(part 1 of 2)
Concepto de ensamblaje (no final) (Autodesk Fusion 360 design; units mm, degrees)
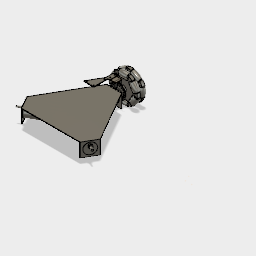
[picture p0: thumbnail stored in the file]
sketch "Sketch1" plane through (0, 0, 0) normal (0, 1, 0) x axis (1, 0, 0)
  line L1 (25, 130) -> (-25, 130)
  line L2 (-125.0833, -43.3494) -> (-25, 130)
  line L3 (100.0833, -86.6506) -> (-100.0833, -86.6506)
  line L4 (25, 130) -> (125.0833, -43.3494)
  line L5 (100.0833, -86.6506) -> (125.0833, -43.3494)
  line L6 (-125.0833, -43.3494) -> (-100.0833, -86.6506)
  line L7 (-50.0833, -86.6506) -> (-100.0833, -86.6506)
  point P3 (-25, 130)
  point P4 (25, 130)
  point P6 (125.0833, -43.3494)
  point P7 (100.0833, -86.6506)
  point P8 (-100.0833, -86.6506)
  point P9 (-125.0833, -43.3494)
  dimension "d2" distance P3 P4 = 50
  dimension "d8" distance P6 P7 = 50
  dimension "d11" distance P8 P9 = 50
  dimension "d12" distance P3 P9 = 200.1666
  dimension "d13" distance P7 P8 = 200.1666
  dimension "d14" distance P4 P6 = 200.1666
extrude "Extrude1" new body sketch "Sketch1" profile of L1 L2 L3 L4 L5 L6 along normal blind 2
sketch "Sketch2" plane through (0, 0, 0) normal (0, -1, 0) x axis (1, 0, 0)
  line L1 (125.0833, 43.3494) -> (25, -130)
  line L2 (100.0833, 86.6506) -> (125.0833, 43.3494)
  line L3 (-100.0833, 86.6506) -> (100.0833, 86.6506)
  line L4 (-125.0833, 43.3494) -> (-100.0833, 86.6506)
  line L5 (-25, -130) -> (-125.0833, 43.3494)
  line L6 (25, -130) -> (-25, -130)
  line L7 (-25, -130) -> (-26.165, -127.9822)
  line L8 (26.1498, -128.0085) -> (25, -130)
  line L9 (-26.165, -127.9822) -> (26.1498, -128.0085)
extrude "Extrude2" add sketch "Sketch2" profile of L1 L5 L6 L7 L8 L9 along normal blind 50
sketch "Sketch3" plane through (0, 0, 0) normal (0, -1, 0) x axis (1, 0, 0)
  line L1 (26.1498, -128.0085) -> (-26.165, -127.9822)
  line L2 (125.0833, 43.3494) -> (26.1498, -128.0085)
  line L3 (100.0833, 86.6506) -> (125.0833, 43.3494)
  line L4 (-100.0833, 86.6506) -> (100.0833, 86.6506)
  line L5 (-125.0833, 43.3494) -> (-100.0833, 86.6506)
  line L6 (-26.165, -127.9822) -> (-125.0833, 43.3494)
  line L7 (125.0833, 43.3494) -> (123.9286, 41.3494)
  line L8 (100.0833, 86.6506) -> (97.7739, 86.6506)
  line L9 (123.9286, 41.3494) -> (97.7739, 86.6506)
  line L10 (-100.0833, 86.6506) -> (-97.7739, 86.6506)
  line L11 (-125.0833, 43.3494) -> (-123.9328, 41.3566)
  line L12 (-97.7739, 86.6506) -> (-123.9328, 41.3566)
extrude "Extrude3" cut of existing geometry blind -5
extrude "Extrude4" add sketch "Sketch3" profile of L2 L3 L4 L5 L6 L7 L8 L9 L10 L11 L12 along normal blind 45
move "Move1"
sketch "Sketch4" plane through (112.5833, 0, 65) normal (0.866, 0, 0.5) x axis (0.5, 0, -0.866)
  line L1 (25, 47) -> (25, 0)
  line L2 (-25, 47) -> (25, 47)
  line L3 (-25, 0) -> (-25, 47)
  line L4 (25, 0) -> (-25, 0)
  line L5 (0, 37.9) -> (0, 42.5)
  circle C1 centre (0, 24) radius 18.5
  circle C2 centre (0, 31.9) radius 6
  point P6 (0, 24)
  point P7 (0, 42.5)
  point P8 (0, 37.9)
  dimension "d31" diameter C1 = 37
  dimension "d32" distance L2 P6 = 23
  dimension "d33" distance L3 P6 = 25
  dimension "d35" distance P7 P8 = 4.6
  dimension "d36" diameter C2 = 12
extrude "Extrude5" cut sketch "Sketch4" profile of C1 C2 against normal blind 0.1
extrude "Extrude6" cut of existing geometry blind -2
sketch "Sketch5" plane through (-112.5833, 0, 65) normal (-0.866, 0, 0.5) x axis (0.5, 0, 0.866)
  line L1 (25, 47) -> (25, 0)
  line L2 (-25, 47) -> (25, 47)
  line L3 (-25, 0) -> (-25, 47)
  line L4 (25, 0) -> (-25, 0)
  line L5 (0, 37.9) -> (0, 42.5)
  circle C1 centre (0, 24) radius 18.5
  circle C2 centre (0, 31.9) radius 6
  point P6 (0, 24)
  point P7 (0, 42.5)
  point P8 (0, 37.9)
  dimension "d41" diameter C1 = 37
  dimension "d42" distance L2 P6 = 23
  dimension "d43" distance L3 P6 = 25
  dimension "d44" distance L4 P6 = 24
  dimension "d45" distance P7 P8 = 4.6
  dimension "d46" diameter C2 = 12
extrude "Extrude7" cut sketch "Sketch5" profile of C1 C2 against normal blind 0.1
extrude "Extrude8" cut of existing geometry blind -2
sketch "Sketch6" plane through (0, 0, -130) normal (0, 0, -1) x axis (-1, 0, 0)
  line L1 (25, 0) -> (-25, 0)
  line L2 (25, 47) -> (25, 0)
  line L3 (-25, 47) -> (25, 47)
  line L4 (-25, 0) -> (-25, 47)
  circle C1 centre (0, 24) radius 18.5
  circle C2 centre (0, 31.9) radius 6
  point P6 (0, 24)
  dimension "d51" diameter C1 = 37
  dimension "d52" distance L3 P6 = 23
  dimension "d53" distance L4 P6 = 25
  dimension "d55" diameter C2 = 12
extrude "Extrude9" cut sketch "Sketch6" profile of C1 C2 against normal blind 0.1
hole "Hole1" HoleDepth 6 HoleDiameter 12 TipAngle 118
sketch "Sketch7" plane through (0, 0, -130) normal (0, 0, -1) x axis (-1, 0, 0)
  line L1 (25, 0) -> (-25, 0)
  line L2 (25, 47) -> (25, 0)
  line L3 (-25, 47) -> (25, 47)
  line L4 (-25, 0) -> (-25, 47)
  circle C1 centre (0, 24) radius 18.5
sketch "Sketch8" plane through (0, 0, 0) normal (1, 0, 0) x axis (0, 0, -1)
sketch "Sketch1"
  circle C1 centre (170, 18.5) radius 18.5
  dimension "d61" diameter C1 = 37
extrude "Extrude1" new body sketch "Sketch1" blind 54.5
sketch "Sketch2" plane through (0, 0, 0) normal (0, 0, -1) x axis (-1, 0, 0)
  circle C1 centre (-170, 18.5) radius 18.5
  circle C2 centre (-170, 26.4) radius 6
  dimension "d66" diameter C2 = 12
extrude "Extrude2" add sketch "Sketch2" profile of C2 along normal blind 6.5
sketch "Sketch3" plane through (0, 0, -6.5) normal (0, 0, -1) x axis (-1, 0, 0)
  circle C1 centre (-170, 26.4) radius 6
  circle C2 centre (-170, 26.4) radius 3
  dimension "d69" diameter C2 = 6
extrude "Extrude3" add sketch "Sketch3" profile of C2 along normal blind 14.5
sketch "Sketch1" plane through (0, 0, 0) normal (0, 1, 0) x axis (1, 0, 0)
sketch "Sketch2" plane through (0, 0, 0) normal (1, 0, 0) x axis (0, 0, -1)
copy_paste_bodies "CopyPasteBodies1"
move "Move1"
copy_paste_bodies "CopyPasteBodies1"
move "Move1"
move "Move1"
position "Position1"
joint "Assemble1" alignAngle 0 alignOffsetX 0 alignOffsetY 0 alignOffsetZ 0
joint "Assemble2" alignAngle 0 alignOffsetX 0 alignOffsetY 0 alignOffsetZ 0
joint "Assemble3" alignAngle 180 alignOffsetX 0 alignOffsetY 0 alignOffsetZ 0
sketch "Sketch1"
  line L1 (233, 59.45) -> (233, 66.5)
  line L2 (235.9, 54.4271) -> (233, 59.45)
  line L3 (233, 70) -> (233, 66.5)
  line L4 (235, 66.5) -> (233, 66.5)
  line L5 (235, 72.697) -> (235, 66.5)
  line L6 (233, 65.5) -> (250, 65.5)
  line L7 (265, 66.5) -> (267, 66.5)
  line L8 (267, 59.45) -> (267, 66.5)
  line L9 (265, 72.697) -> (265, 66.5)
  line L10 (264.1, 54.4271) -> (267, 59.45)
  line L11 (267, 65.5) -> (250, 65.5)
  line L12 (267, 70) -> (267, 66.5)
  line L13 (264.1, 54.4271) -> (235.9, 54.4271)
  line L14 (202.5289, 32.7776) -> (205.5599, 31.0276)
  line L15 (211.6654, 27.5026) -> (205.5599, 31.0276)
  line L16 (231.5654, 51.9245) -> (228.6654, 56.9474)
  line L17 (206.426, 30.5276) -> (214.926, 45.25)
  line L18 (231.5654, 51.9245) -> (217.4654, 27.5026)
  line L19 (217.4654, 27.5026) -> (211.6654, 27.5026)
  line L20 (228.6654, 56.9474) -> (222.5599, 60.4724)
  line L21 (201.1932, 35.8581) -> (206.5599, 32.7596)
  line L22 (223.426, 59.9724) -> (214.926, 45.25)
  line L23 (216.1932, 61.8389) -> (221.5599, 58.7404)
  line L24 (221.5599, 58.7404) -> (222.5599, 60.4724)
  line L25 (206.5599, 32.7596) -> (205.5599, 31.0276)
  line L26 (219.5289, 62.2224) -> (222.5599, 60.4724)
  line L27 (219.5289, -12.2224) -> (222.5599, -10.4724)
  line L28 (228.6654, -6.9474) -> (222.5599, -10.4724)
  line L29 (217.4654, 22.4974) -> (211.6654, 22.4974)
  line L30 (223.426, -9.9724) -> (214.926, 4.75)
  line L31 (217.4654, 22.4974) -> (231.5654, -1.9245)
  line L32 (231.5654, -1.9245) -> (228.6654, -6.9474)
  line L33 (211.6654, 22.4974) -> (205.5599, 18.9724)
  line L34 (216.1932, -11.8389) -> (221.5599, -8.7404)
  line L35 (206.426, 19.4724) -> (214.926, 4.75)
  line L36 (201.1932, 14.1419) -> (206.5599, 17.2404)
  line L37 (206.5599, 17.2404) -> (205.5599, 18.9724)
  line L38 (221.5599, -8.7404) -> (222.5599, -10.4724)
  line L39 (202.5289, 17.2224) -> (205.5599, 18.9724)
  line L40 (267, -20) -> (267, -16.5)
  line L41 (267, -9.45) -> (267, -16.5)
  line L42 (235.9, -4.4271) -> (233, -9.45)
  line L43 (267, -15.5) -> (250, -15.5)
  line L44 (235.9, -4.4271) -> (264.1, -4.4271)
  line L45 (264.1, -4.4271) -> (267, -9.45)
  line L46 (233, -9.45) -> (233, -16.5)
  line L47 (265, -22.697) -> (265, -16.5)
  line L48 (233, -15.5) -> (250, -15.5)
  line L49 (235, -22.697) -> (235, -16.5)
  line L50 (235, -16.5) -> (233, -16.5)
  line L51 (265, -16.5) -> (267, -16.5)
  line L52 (233, -20) -> (233, -16.5)
  line L53 (297.4711, 17.2224) -> (294.4401, 18.9724)
  line L54 (288.3346, 22.4974) -> (294.4401, 18.9724)
  line L55 (268.4346, -1.9245) -> (271.3346, -6.9474)
  line L56 (293.574, 19.4724) -> (285.074, 4.75)
  line L57 (268.4346, -1.9245) -> (282.5346, 22.4974)
  line L58 (282.5346, 22.4974) -> (288.3346, 22.4974)
  line L59 (271.3346, -6.9474) -> (277.4401, -10.4724)
  line L60 (298.8068, 14.1419) -> (293.4401, 17.2404)
  line L61 (276.574, -9.9724) -> (285.074, 4.75)
  line L62 (283.8068, -11.8389) -> (278.4401, -8.7404)
  line L63 (278.4401, -8.7404) -> (277.4401, -10.4724)
  line L64 (293.4401, 17.2404) -> (294.4401, 18.9724)
  line L65 (280.4711, -12.2224) -> (277.4401, -10.4724)
  line L66 (280.4711, 62.2224) -> (277.4401, 60.4724)
  line L67 (271.3346, 56.9474) -> (277.4401, 60.4724)
  line L68 (282.5346, 27.5026) -> (288.3346, 27.5026)
  line L69 (276.574, 59.9724) -> (285.074, 45.25)
  line L70 (282.5346, 27.5026) -> (268.4346, 51.9245)
  line L71 (268.4346, 51.9245) -> (271.3346, 56.9474)
  line L72 (288.3346, 27.5026) -> (294.4401, 31.0276)
  line L73 (283.8068, 61.8389) -> (278.4401, 58.7404)
  line L74 (293.574, 30.5276) -> (285.074, 45.25)
  line L75 (298.8068, 35.8581) -> (293.4401, 32.7596)
  line L76 (293.4401, 32.7596) -> (294.4401, 31.0276)
  line L77 (278.4401, 58.7404) -> (277.4401, 60.4724)
  line L78 (297.4711, 32.7776) -> (294.4401, 31.0276)
  arc A1 centre (250, 25) radius 50 clockwise from (235, 72.697) to (265, 72.697)
  arc A2 centre (250, 25) radius 50 clockwise from (201.1932, 35.8581) to (216.1932, 61.8389)
  arc A3 centre (250, 25) radius 50 clockwise from (216.1932, -11.8389) to (201.1932, 14.1419)
  arc A4 centre (250, 25) radius 50 clockwise from (265, -22.697) to (235, -22.697)
  arc A5 centre (250, 25) radius 50 clockwise from (298.8068, 14.1419) to (283.8068, -11.8389)
  arc A6 centre (250, 25) radius 50 clockwise from (283.8068, 61.8389) to (298.8068, 35.8581)
  arc A7 centre (250, 25) radius 48.1041 clockwise from (202.5289, 17.2224) to (202.5289, 32.7776)
  arc A8 centre (250, 25) radius 48.1041 clockwise from (233, -20) to (219.5289, -12.2224)
  arc A9 centre (250, 25) radius 48.1041 clockwise from (280.4711, -12.2224) to (267, -20)
  arc A10 centre (250, 25) radius 48.1041 clockwise from (297.4711, 32.7776) to (297.4711, 17.2224)
  arc A11 centre (250, 25) radius 48.1041 clockwise from (267, 70) to (280.4711, 62.2224)
  arc A12 centre (250, 25) radius 48.1041 clockwise from (219.5289, 62.2224) to (233, 70)
  point P3 (233, 66.5)
  point P4 (233, 59.45)
  point P5 (235.9, 54.4271)
  point P6 (233, 70)
  point P2 (250, 65.5)
  point P15 (250, 75)
  point P8 (235, 72.697)
  dimension "d112" distance P3 P4 = 7.05
  dimension "d114" distance P4 P5 = 5.8
  dimension "d115" distance P3 P6 = 3.5
  dimension "d116" distance L4 L6 = 1
  dimension "d117" distance P2 P15 = 9.5
  dimension "d118" distance P8 L6 = 7.197
extrude "Extrude1" new body sketch "Sketch1" profile of L1 L2 L3 L8 L10 L12 L13 L14 L15 L16 L18 L19 L20 L26 L27 L28 L29 L31 L32 L33 L39 L40 L41 L42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 blind 5
sketch "Sketch3" plane through (0, 0, 119.3234) normal (0, 0, -1) x axis (-1, 0, 0)
  circle C1 centre (-17.736, 26.4) radius 3
revolve "Revolve1" sketch "Sketch1" AlongAngle 360
revolve "Revolve3" sketch "Sketch1" AlongAngle 360
revolve "Revolve4" sketch "Sketch1" AlongAngle 360
revolve "Revolve2" sketch "Sketch1" AlongAngle 360
revolve "Revolve5" sketch "Sketch1" AlongAngle 360
revolve "Revolve6" sketch "Sketch1" AlongAngle 360
extrude "Extrude2" cut of existing geometry blind -5
extrude "Extrude3" add sketch "Sketch1" profile of L1 L2 L3 L8 L10 L12 L13 L14 L15 L16 L18 L19 L20 L26 L27 L28 L29 L31 L32 L33 L39 L40 L41 L42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 distance 5
sketch "Sketch2" plane through (0, 0, 5) normal (0, 0, 1) x axis (1, 0, 0)
  line L1 (233, 70) -> (233, 59.45)
  line L2 (228.6654, 56.9474) -> (219.5289, 62.2224)
  line L3 (231.5654, 51.9245) -> (228.6654, 56.9474)
  line L4 (217.4654, 27.5026) -> (231.5654, 51.9245)
  line L5 (211.6654, 27.5026) -> (217.4654, 27.5026)
  line L6 (202.5289, 32.7776) -> (211.6654, 27.5026)
  line L7 (211.6654, 22.4974) -> (202.5289, 17.2224)
  line L8 (217.4654, 22.4974) -> (211.6654, 22.4974)
  line L9 (231.5654, -1.9245) -> (217.4654, 22.4974)
  line L10 (228.6654, -6.9474) -> (231.5654, -1.9245)
  line L11 (219.5289, -12.2224) -> (228.6654, -6.9474)
  line L12 (233, -9.45) -> (233, -20)
  line L13 (235.9, -4.4271) -> (233, -9.45)
  line L14 (264.1, -4.4271) -> (235.9, -4.4271)
  line L15 (267, -9.45) -> (264.1, -4.4271)
  line L16 (267, -20) -> (267, -9.45)
  line L17 (271.3346, -6.9474) -> (280.4711, -12.2224)
  line L18 (268.4346, -1.9245) -> (271.3346, -6.9474)
  line L19 (282.5346, 22.4974) -> (268.4346, -1.9245)
  line L20 (288.3346, 22.4974) -> (282.5346, 22.4974)
  line L21 (297.4711, 17.2224) -> (288.3346, 22.4974)
  line L22 (288.3346, 27.5026) -> (297.4711, 32.7776)
  line L23 (282.5346, 27.5026) -> (288.3346, 27.5026)
  line L24 (268.4346, 51.9245) -> (282.5346, 27.5026)
  line L25 (271.3346, 56.9474) -> (268.4346, 51.9245)
  line L26 (280.4711, 62.2224) -> (271.3346, 56.9474)
  line L27 (267, 59.45) -> (267, 70)
  line L28 (264.1, 54.4271) -> (267, 59.45)
  line L29 (235.9, 54.4271) -> (264.1, 54.4271)
  line L30 (233, 59.45) -> (235.9, 54.4271)
  arc A1 centre (250, 25) radius 48.1041 clockwise from (219.5289, 62.2224) to (233, 70)
  arc A2 centre (250, 25) radius 48.1041 clockwise from (202.5289, 17.2224) to (202.5289, 32.7776)
  arc A3 centre (250, 25) radius 48.1041 clockwise from (233, -20) to (219.5289, -12.2224)
  arc A4 centre (250, 25) radius 48.1041 clockwise from (280.4711, -12.2224) to (267, -20)
  arc A5 centre (250, 25) radius 48.1041 clockwise from (297.4711, 32.7776) to (297.4711, 17.2224)
  arc A6 centre (250, 25) radius 48.1041 clockwise from (267, 70) to (280.4711, 62.2224)
copy_paste_bodies "CopyPasteBodies1"
move "Move1"
move "Move2" RotateAngle -30
sketch "Sketch3" plane through (0, 0, -5) normal (0, 0, -1) x axis (-1, 0, 0)
  line L1 (-233, 59.45) -> (-233, 70)
  line L2 (-235.9, 54.4271) -> (-233, 59.45)
  line L3 (-264.1, 54.4271) -> (-235.9, 54.4271)
  line L4 (-267, 59.45) -> (-264.1, 54.4271)
  line L5 (-267, 70) -> (-267, 59.45)
  line L6 (-271.3346, 56.9474) -> (-280.4711, 62.2224)
  line L7 (-268.4346, 51.9245) -> (-271.3346, 56.9474)
  line L8 (-282.5346, 27.5026) -> (-268.4346, 51.9245)
  line L9 (-288.3346, 27.5026) -> (-282.5346, 27.5026)
  line L10 (-297.4711, 32.7776) -> (-288.3346, 27.5026)
  line L11 (-288.3346, 22.4974) -> (-297.4711, 17.2224)
  line L12 (-282.5346, 22.4974) -> (-288.3346, 22.4974)
  line L13 (-268.4346, -1.9245) -> (-282.5346, 22.4974)
  line L14 (-271.3346, -6.9474) -> (-268.4346, -1.9245)
  line L15 (-280.4711, -12.2224) -> (-271.3346, -6.9474)
  line L16 (-267, -9.45) -> (-267, -20)
  line L17 (-264.1, -4.4271) -> (-267, -9.45)
  line L18 (-235.9, -4.4271) -> (-264.1, -4.4271)
  line L19 (-233, -9.45) -> (-235.9, -4.4271)
  line L20 (-233, -20) -> (-233, -9.45)
  line L21 (-228.6654, -6.9474) -> (-219.5289, -12.2224)
  line L22 (-231.5654, -1.9245) -> (-228.6654, -6.9474)
  line L23 (-217.4654, 22.4974) -> (-231.5654, -1.9245)
  line L24 (-211.6654, 22.4974) -> (-217.4654, 22.4974)
  line L25 (-202.5289, 17.2224) -> (-211.6654, 22.4974)
  line L26 (-211.6654, 27.5026) -> (-202.5289, 32.7776)
  line L27 (-217.4654, 27.5026) -> (-211.6654, 27.5026)
  line L28 (-231.5654, 51.9245) -> (-217.4654, 27.5026)
  line L29 (-228.6654, 56.9474) -> (-231.5654, 51.9245)
  line L30 (-219.5289, 62.2224) -> (-228.6654, 56.9474)
  line L31 (-232.6795, 15) -> (-250, 5)
  line L32 (-232.6795, 35) -> (-232.6795, 15)
  line L33 (-250, 45) -> (-232.6795, 35)
  line L34 (-267.3205, 35) -> (-250, 45)
  line L35 (-267.3205, 15) -> (-267.3205, 35)
  line L36 (-250, 5) -> (-267.3205, 15)
  arc A1 centre (-250, 25) radius 48.1041 clockwise from (-280.4711, 62.2224) to (-267, 70)
  arc A2 centre (-250, 25) radius 48.1041 clockwise from (-297.4711, 17.2224) to (-297.4711, 32.7776)
  arc A3 centre (-250, 25) radius 48.1041 clockwise from (-267, -20) to (-280.4711, -12.2224)
  arc A4 centre (-250, 25) radius 48.1041 clockwise from (-219.5289, -12.2224) to (-233, -20)
  arc A5 centre (-250, 25) radius 48.1041 clockwise from (-202.5289, 32.7776) to (-202.5289, 17.2224)
  arc A6 centre (-250, 25) radius 48.1041 clockwise from (-233, 70) to (-219.5289, 62.2224)
  point P39 (-250, 5)
  point P45 (-250, 25)
  dimension "d135" distance P39 P45 = 20
extrude "Extrude4" add sketch "Sketch3" profile of L31 L32 L33 L34 L35 L36 along normal blind 12
sketch "Sketch1" plane through (0, 0, -3.4476) normal (0, 0, 1) x axis (1, 0, 0)
  line L1 (383.04, 72.4711) -> (377.765, 63.3346)
  line L2 (372.7599, 63.3346) -> (367.4849, 72.4711)
  line L3 (372.7599, 57.5346) -> (372.7599, 63.3346)
  line L4 (348.338, 43.4346) -> (372.7599, 57.5346)
  line L5 (343.315, 46.3346) -> (348.338, 43.4346)
  line L6 (338.04, 55.4711) -> (343.315, 46.3346)
  line L7 (340.8125, 42) -> (330.2625, 42)
  line L8 (345.8354, 39.1) -> (340.8125, 42)
  line L9 (345.8354, 10.9) -> (345.8354, 39.1)
  line L10 (340.8125, 8) -> (345.8354, 10.9)
  line L11 (330.2625, 8) -> (340.8125, 8)
  line L12 (343.315, 3.6654) -> (338.04, -5.4711)
  line L13 (348.338, 6.5654) -> (343.315, 3.6654)
  line L14 (372.7599, -7.5346) -> (348.338, 6.5654)
  line L15 (372.7599, -13.3346) -> (372.7599, -7.5346)
  line L16 (367.4849, -22.4711) -> (372.7599, -13.3346)
  line L17 (377.765, -13.3346) -> (383.04, -22.4711)
  line L18 (377.765, -7.5346) -> (377.765, -13.3346)
  line L19 (402.1869, 6.5654) -> (377.765, -7.5346)
  line L20 (407.2099, 3.6654) -> (402.1869, 6.5654)
  line L21 (412.4849, -5.4711) -> (407.2099, 3.6654)
  line L22 (409.7125, 8) -> (420.2625, 8)
  line L23 (404.6895, 10.9) -> (409.7125, 8)
  line L24 (404.6895, 39.1) -> (404.6895, 10.9)
  line L25 (409.7125, 42) -> (404.6895, 39.1)
  line L26 (420.2625, 42) -> (409.7125, 42)
  line L27 (407.2099, 46.3346) -> (412.4849, 55.4711)
  line L28 (402.1869, 43.4346) -> (407.2099, 46.3346)
  line L29 (377.765, 57.5346) -> (402.1869, 43.4346)
  line L30 (377.765, 63.3346) -> (377.765, 57.5346)
  line L31 (392.583, 15) -> (375.2625, 5)
  line L32 (392.583, 35) -> (392.583, 15)
  line L33 (375.2625, 45) -> (392.583, 35)
  line L34 (357.942, 35) -> (375.2625, 45)
  line L35 (357.942, 15) -> (357.942, 35)
  line L36 (375.2625, 5) -> (357.942, 15)
  arc A1 centre (375.2625, 25) radius 48.1041 clockwise from (367.4849, 72.4711) to (383.04, 72.4711)
  arc A2 centre (375.2625, 25) radius 48.1041 clockwise from (330.2625, 42) to (338.04, 55.4711)
  arc A3 centre (375.2625, 25) radius 48.1041 clockwise from (338.04, -5.4711) to (330.2625, 8)
  arc A4 centre (375.2625, 25) radius 48.1041 clockwise from (383.04, -22.4711) to (367.4849, -22.4711)
  arc A5 centre (375.2625, 25) radius 48.1041 clockwise from (420.2625, 8) to (412.4849, -5.4711)
  arc A6 centre (375.2625, 25) radius 48.1041 clockwise from (412.4849, 55.4711) to (420.2625, 42)
  point P39 (375.2625, 5)
  point P45 (375.2625, 25)
  dimension "d139" distance P39 P45 = 20
extrude "Extrude1" cut sketch "Sketch1" profile of L31 L32 L33 L34 L35 L36 against normal blind 3
sketch "Sketch4" plane through (0, 0, -17) normal (0, 0, -1) x axis (-1, 0, 0)
  line L1 (-250, 5) -> (-267.3205, 15)
  line L2 (-232.6795, 15) -> (-250, 5)
  line L3 (-232.6795, 35) -> (-232.6795, 15)
  line L4 (-250, 45) -> (-232.6795, 35)
  line L5 (-267.3205, 35) -> (-250, 45)
  line L6 (-267.3205, 15) -> (-267.3205, 35)
  circle C1 centre (-250, 37.5) radius 1.5
  circle C2 centre (-260.8253, 18.75) radius 1.5
  circle C3 centre (-239.1747, 18.75) radius 1.5
  dimension "d143" diameter C1 = 3
  dimension "d144" diameter C2 = 3
  dimension "d145" diameter C3 = 3
sketch "Sketch5" plane through (267.3205, 0, 0) normal (1, 0, 0) x axis (0, 0, -1)
  line L1 (5, 15) -> (5, 35)
  line L2 (17, 15) -> (5, 15)
  line L3 (17, 35) -> (17, 15)
  line L4 (5, 35) -> (17, 35)
  dimension "d148" distance L1 L3 = 12
extrude "Extrude5" cut sketch "Sketch4" profile of C1 C2 C3 against normal blind 10
sketch "Sketch2" plane through (0, 0, -6.4476) normal (0, 0, 1) x axis (1, 0, 0)
  line L1 (375.2625, 5) -> (357.942, 15)
  line L2 (392.583, 15) -> (375.2625, 5)
  line L3 (392.583, 35) -> (392.583, 15)
  line L4 (375.2625, 45) -> (392.583, 35)
  line L5 (357.942, 35) -> (375.2625, 45)
  line L6 (357.942, 15) -> (357.942, 35)
  circle C1 centre (375.2625, 37.5) radius 1.5
  circle C2 centre (386.0878, 18.75) radius 1.5
  circle C3 centre (364.4371, 18.75) radius 1.5
  dimension "d152" diameter C1 = 3
  dimension "d153" diameter C2 = 3
  dimension "d154" diameter C3 = 3
extrude "Extrude2" cut sketch "Sketch2" profile of C1 C2 C3 against normal blind 7
sketch "Sketch6" plane through (0, 0, -17) normal (0, 0, -1) x axis (-1, 0, 0)
  circle C1 centre (-260.8253, 18.75) radius 1.5
  circle C2 centre (-239.1747, 18.75) radius 1.5
  circle C3 centre (-250, 37.5) radius 1.5
cylinder_primitive "CylinderPrimitive2" Height 17 Diameter 3
sketch "Sketch3" plane through (0, 47, 0) normal (0, 1, 0) x axis (-1, 0, 0)
sketch "Sketch4" plane through (0, 0, 0) normal (0, 0, -1) x axis (-1, 0, 0)
  line L1 (-506, 4.9822) -> (-508.0154, 1.527)
  line L2 (-507.9846, 8.4552) -> (-506, 4.9822)
  line L3 (-511.9846, 8.473) -> (-507.9846, 8.4552)
  line L4 (-514, 5.0178) -> (-511.9846, 8.473)
  line L5 (-512.0154, 1.5448) -> (-514, 5.0178)
  line L6 (-508.0154, 1.527) -> (-512.0154, 1.5448)
  circle C1 centre (-510, 5) radius 1.5
  point P3 (-508.0154, 1.527)
  point P9 (-510, 5)
  dimension "d159" distance P3 P9 = 4
extrude "Extrude1" add sketch "Sketch4" along normal blind 2
thread "Thread2"
thread "Thread1"
thread "Thread2"
thread "Thread3"
copy_paste_bodies "CopyPasteBodies1"
move "Move1"
sketch "Sketch3" plane through (0, 0, -5) normal (0, 0, -1) x axis (-1, 0, 0)
  line L1 (-267.3205, 35) -> (-267.3205, 15)
  line L2 (-250, 45) -> (-267.3205, 35)
  line L3 (-232.6795, 35) -> (-250, 45)
  line L4 (-232.6795, 15) -> (-232.6795, 35)
  line L5 (-250, 5) -> (-232.6795, 15)
  line L6 (-267.3205, 15) -> (-250, 5)
  line L7 (-233, 59.45) -> (-233, 70)
  line L8 (-235.9, 54.4271) -> (-233, 59.45)
  line L9 (-264.1, 54.4271) -> (-235.9, 54.4271)
  line L10 (-267, 59.45) -> (-264.1, 54.4271)
  line L11 (-267, 70) -> (-267, 59.45)
  line L12 (-271.3346, 56.9474) -> (-280.4711, 62.2224)
  line L13 (-268.4346, 51.9245) -> (-271.3346, 56.9474)
  line L14 (-282.5346, 27.5026) -> (-268.4346, 51.9245)
  line L15 (-288.3346, 27.5026) -> (-282.5346, 27.5026)
  line L16 (-297.4711, 32.7776) -> (-288.3346, 27.5026)
  line L17 (-288.3346, 22.4974) -> (-297.4711, 17.2224)
  line L18 (-282.5346, 22.4974) -> (-288.3346, 22.4974)
  line L19 (-268.4346, -1.9245) -> (-282.5346, 22.4974)
  line L20 (-271.3346, -6.9474) -> (-268.4346, -1.9245)
  line L21 (-280.4711, -12.2224) -> (-271.3346, -6.9474)
  line L22 (-267, -9.45) -> (-267, -20)
  line L23 (-264.1, -4.4271) -> (-267, -9.45)
  line L24 (-235.9, -4.4271) -> (-264.1, -4.4271)
  line L25 (-233, -9.45) -> (-235.9, -4.4271)
  line L26 (-233, -20) -> (-233, -9.45)
  line L27 (-228.6654, -6.9474) -> (-219.5289, -12.2224)
  line L28 (-231.5654, -1.9245) -> (-228.6654, -6.9474)
  line L29 (-217.4654, 22.4974) -> (-231.5654, -1.9245)
  line L30 (-211.6654, 22.4974) -> (-217.4654, 22.4974)
  line L31 (-202.5289, 17.2224) -> (-211.6654, 22.4974)
  line L32 (-211.6654, 27.5026) -> (-202.5289, 32.7776)
  line L33 (-217.4654, 27.5026) -> (-211.6654, 27.5026)
  line L34 (-231.5654, 51.9245) -> (-217.4654, 27.5026)
  line L35 (-228.6654, 56.9474) -> (-231.5654, 51.9245)
  line L36 (-219.5289, 62.2224) -> (-228.6654, 56.9474)
  arc A1 centre (-250, 25) radius 48.1041 clockwise from (-280.4711, 62.2224) to (-267, 70)
  arc A2 centre (-250, 25) radius 48.1041 clockwise from (-297.4711, 17.2224) to (-297.4711, 32.7776)
  arc A3 centre (-250, 25) radius 48.1041 clockwise from (-267, -20) to (-280.4711, -12.2224)
  arc A4 centre (-250, 25) radius 48.1041 clockwise from (-219.5289, -12.2224) to (-233, -20)
  arc A5 centre (-250, 25) radius 48.1041 clockwise from (-202.5289, 32.7776) to (-202.5289, 17.2224)
  arc A6 centre (-250, 25) radius 48.1041 clockwise from (-233, 70) to (-219.5289, 62.2224)
  circle C1 centre (-250, 25) radius 20
extrude "Extrude14" add sketch "Sketch3" profile of L1 L2 L3 L4 L5 L6 A4 C1 along normal blind 12
sketch "Sketch4" plane through (0, 0, -6.4476) normal (0, 0, 1) x axis (1, 0, 0)
  circle C1 centre (364.4371, 18.75) radius 1.2645
  circle C2 centre (386.0878, 18.75) radius 1.2645
  circle C3 centre (375.2625, 37.5) radius 1.2645
sketch "Sketch5" plane through (0, 0, -3.4476) normal (0, 0, 1) x axis (1, 0, 0)
  line L1 (375.2625, 5) -> (392.583, 15)
  line L2 (357.942, 15) -> (375.2625, 5)
  line L3 (357.942, 35) -> (357.942, 15)
  line L4 (375.2625, 45) -> (357.942, 35)
  line L5 (392.583, 35) -> (375.2625, 45)
  line L6 (392.583, 15) -> (392.583, 35)
  line L7 (383.04, 72.4711) -> (377.765, 63.3346)
  line L8 (372.7599, 63.3346) -> (367.4849, 72.4711)
  line L9 (372.7599, 57.5346) -> (372.7599, 63.3346)
  line L10 (348.338, 43.4346) -> (372.7599, 57.5346)
  line L11 (343.315, 46.3346) -> (348.338, 43.4346)
  line L12 (338.04, 55.4711) -> (343.315, 46.3346)
  line L13 (340.8125, 42) -> (330.2625, 42)
  line L14 (345.8354, 39.1) -> (340.8125, 42)
  line L15 (345.8354, 10.9) -> (345.8354, 39.1)
  line L16 (340.8125, 8) -> (345.8354, 10.9)
  line L17 (330.2625, 8) -> (340.8125, 8)
  line L18 (343.315, 3.6654) -> (338.04, -5.4711)
  line L19 (348.338, 6.5654) -> (343.315, 3.6654)
  line L20 (372.7599, -7.5346) -> (348.338, 6.5654)
  line L21 (372.7599, -13.3346) -> (372.7599, -7.5346)
  line L22 (367.4849, -22.4711) -> (372.7599, -13.3346)
  line L23 (377.765, -13.3346) -> (383.04, -22.4711)
  line L24 (377.765, -7.5346) -> (377.765, -13.3346)
  line L25 (402.1869, 6.5654) -> (377.765, -7.5346)
  line L26 (407.2099, 3.6654) -> (402.1869, 6.5654)
  line L27 (412.4849, -5.4711) -> (407.2099, 3.6654)
  line L28 (409.7125, 8) -> (420.2625, 8)
  line L29 (404.6895, 10.9) -> (409.7125, 8)
  line L30 (404.6895, 39.1) -> (404.6895, 10.9)
  line L31 (409.7125, 42) -> (404.6895, 39.1)
  line L32 (420.2625, 42) -> (409.7125, 42)
  line L33 (407.2099, 46.3346) -> (412.4849, 55.4711)
  line L34 (402.1869, 43.4346) -> (407.2099, 46.3346)
  line L35 (377.765, 57.5346) -> (402.1869, 43.4346)
  line L36 (377.765, 63.3346) -> (377.765, 57.5346)
  arc A1 centre (375.2625, 25) radius 48.1041 clockwise from (367.4849, 72.4711) to (383.04, 72.4711)
  arc A2 centre (375.2625, 25) radius 48.1041 clockwise from (330.2625, 42) to (338.04, 55.4711)
  arc A3 centre (375.2625, 25) radius 48.1041 clockwise from (338.04, -5.4711) to (330.2625, 8)
  arc A4 centre (375.2625, 25) radius 48.1041 clockwise from (383.04, -22.4711) to (367.4849, -22.4711)
  arc A5 centre (375.2625, 25) radius 48.1041 clockwise from (420.2625, 8) to (412.4849, -5.4711)
  arc A6 centre (375.2625, 25) radius 48.1041 clockwise from (412.4849, 55.4711) to (420.2625, 42)
  circle C1 centre (375.2625, 25) radius 20
extrude "Extrude3" cut sketch "Sketch5" profile of L1 L2 L3 L4 L5 L6 C1 against normal blind 3
sketch "Sketch6" plane through (0, 0, 5) normal (0, 0, 1) x axis (1, 0, 0)
copy_paste_bodies "CopyPasteBodies1"
move "Move1"
copy_paste "CutPaste1"
copy_paste "CutPaste2"
sketch "Sketch7" plane through (0, 0, 5) normal (0, 0, 1) x axis (1, 0, 0)
  line L1 (233, 70) -> (233, 59.45)
  line L2 (228.6654, 56.9474) -> (219.5289, 62.2224)
  line L3 (231.5654, 51.9245) -> (228.6654, 56.9474)
  line L4 (217.4654, 27.5026) -> (231.5654, 51.9245)
  line L5 (211.6654, 27.5026) -> (217.4654, 27.5026)
  line L6 (202.5289, 32.7776) -> (211.6654, 27.5026)
  line L7 (211.6654, 22.4974) -> (202.5289, 17.2224)
  line L8 (217.4654, 22.4974) -> (211.6654, 22.4974)
  line L9 (231.5654, -1.9245) -> (217.4654, 22.4974)
  line L10 (228.6654, -6.9474) -> (231.5654, -1.9245)
  line L11 (219.5289, -12.2224) -> (228.6654, -6.9474)
  line L12 (233, -9.45) -> (233, -20)
  line L13 (235.9, -4.4271) -> (233, -9.45)
  line L14 (264.1, -4.4271) -> (235.9, -4.4271)
  line L15 (267, -9.45) -> (264.1, -4.4271)
  line L16 (267, -20) -> (267, -9.45)
  line L17 (271.3346, -6.9474) -> (280.4711, -12.2224)
  line L18 (268.4346, -1.9245) -> (271.3346, -6.9474)
  line L19 (282.5346, 22.4974) -> (268.4346, -1.9245)
  line L20 (288.3346, 22.4974) -> (282.5346, 22.4974)
  line L21 (297.4711, 17.2224) -> (288.3346, 22.4974)
  line L22 (288.3346, 27.5026) -> (297.4711, 32.7776)
  line L23 (282.5346, 27.5026) -> (288.3346, 27.5026)
  line L24 (268.4346, 51.9245) -> (282.5346, 27.5026)
  line L25 (271.3346, 56.9474) -> (268.4346, 51.9245)
  line L26 (280.4711, 62.2224) -> (271.3346, 56.9474)
  line L27 (267, 59.45) -> (267, 70)
  line L28 (264.1, 54.4271) -> (267, 59.45)
  line L29 (235.9, 54.4271) -> (264.1, 54.4271)
  line L30 (233, 59.45) -> (235.9, 54.4271)
  arc A1 centre (250, 25) radius 48.1041 clockwise from (219.5289, 62.2224) to (233, 70)
  arc A2 centre (250, 25) radius 48.1041 clockwise from (202.5289, 17.2224) to (202.5289, 32.7776)
  arc A3 centre (250, 25) radius 48.1041 clockwise from (233, -20) to (219.5289, -12.2224)
  arc A4 centre (250, 25) radius 48.1041 clockwise from (280.4711, -12.2224) to (267, -20)
  arc A5 centre (250, 25) radius 48.1041 clockwise from (297.4711, 32.7776) to (297.4711, 17.2224)
  arc A6 centre (250, 25) radius 48.1041 clockwise from (267, 70) to (280.4711, 62.2224)
  circle C1 centre (250, 25) radius 7.5
  circle C2 centre (250, 25) radius 3
  dimension "d210" diameter C1 = 15
  dimension "d211" diameter C2 = 6
extrude "Extrude6" add sketch "Sketch7" profile of C1 C2 along normal blind 14.5
sketch "Sketch8" plane through (178.842, -103.2545, 0) normal (0.866, -0.5, 0) x axis (0, 0, -1)
  line L1 (-5, 114.1161) -> (5, 114.1161)
  line L2 (-5, 108.3161) -> (-5, 114.1161)
  line L3 (5, 108.3161) -> (-5, 108.3161)
  line L4 (5, 114.1161) -> (5, 108.3161)
sketch "Sketch9" plane through (0, 0, 0) normal (0, 1, 0) x axis (1, 0, 0)
extrude "Extrude7" add of existing geometry blind 1.5
copy_paste "CutPaste1"
copy_paste "CutPaste2"
extrude "Extrude8" add of existing geometry blind 16
move "Move4"
extrude "Extrude9" cut of existing geometry blind -16
sketch "Sketch1" plane through (0, 0, 5) normal (0, 0, 1) x axis (1, 0, 0)
  line L1 (233, 70) -> (233, 59.45)
  line L2 (228.6654, 56.9474) -> (219.5289, 62.2224)
  line L3 (231.5654, 51.9245) -> (228.6654, 56.9474)
  line L4 (217.4654, 27.5026) -> (231.5654, 51.9245)
  line L5 (211.6654, 27.5026) -> (217.4654, 27.5026)
  line L6 (202.5289, 32.7776) -> (211.6654, 27.5026)
  line L7 (211.6654, 22.4974) -> (202.5289, 17.2224)
  line L8 (217.4654, 22.4974) -> (211.6654, 22.4974)
  line L9 (231.5654, -1.9245) -> (217.4654, 22.4974)
  line L10 (228.6654, -6.9474) -> (231.5654, -1.9245)
  line L11 (219.5289, -12.2224) -> (228.6654, -6.9474)
  line L12 (233, -9.45) -> (233, -20)
  line L13 (235.9, -4.4271) -> (233, -9.45)
  line L14 (264.1, -4.4271) -> (235.9, -4.4271)
  line L15 (267, -9.45) -> (264.1, -4.4271)
  line L16 (267, -20) -> (267, -9.45)
  line L17 (271.3346, -6.9474) -> (280.4711, -12.2224)
  line L18 (268.4346, -1.9245) -> (271.3346, -6.9474)
  line L19 (282.5346, 22.4974) -> (268.4346, -1.9245)
  line L20 (288.3346, 22.4974) -> (282.5346, 22.4974)
  line L21 (297.4711, 17.2224) -> (288.3346, 22.4974)
  line L22 (288.3346, 27.5026) -> (297.4711, 32.7776)
  line L23 (282.5346, 27.5026) -> (288.3346, 27.5026)
  line L24 (268.4346, 51.9245) -> (282.5346, 27.5026)
  line L25 (271.3346, 56.9474) -> (268.4346, 51.9245)
  line L26 (280.4711, 62.2224) -> (271.3346, 56.9474)
  line L27 (267, 59.45) -> (267, 70)
  line L28 (264.1, 54.4271) -> (267, 59.45)
  line L29 (235.9, 54.4271) -> (264.1, 54.4271)
  line L30 (233, 59.45) -> (235.9, 54.4271)
  line L31 (250, 37) -> (260.3923, 19)
  line L32 (239.6077, 19) -> (250, 37)
  line L33 (260.3923, 19) -> (239.6077, 19)
  arc A1 centre (250, 25) radius 48.1041 clockwise from (219.5289, 62.2224) to (233, 70)
  arc A2 centre (250, 25) radius 48.1041 clockwise from (202.5289, 17.2224) to (202.5289, 32.7776)
  arc A3 centre (250, 25) radius 48.1041 clockwise from (233, -20) to (219.5289, -12.2224)
  arc A4 centre (250, 25) radius 48.1041 clockwise from (280.4711, -12.2224) to (267, -20)
  arc A5 centre (250, 25) radius 48.1041 clockwise from (297.4711, 32.7776) to (297.4711, 17.2224)
  arc A6 centre (250, 25) radius 48.1041 clockwise from (267, 70) to (280.4711, 62.2224)
  circle C1 centre (250, 25) radius 3
  point P43 (250, 25)
  dimension "d254" diameter C1 = 6
  dimension "d255" distance P43 L33 = 6
joint "Assemble8" alignAngle 0 alignOffsetX 0 alignOffsetY 0 alignOffsetZ 0
joint "Assemble9" alignAngle 0 alignOffsetX 0 alignOffsetY 0 alignOffsetZ 0
joint "Assemble10" alignAngle 0 alignOffsetX 0 alignOffsetY 0 alignOffsetZ 0
joint "Assemble11" alignAngle 0 alignOffsetX 0 alignOffsetY 0 alignOffsetZ 0
sketch "Sketch7" plane through (0, 0, 5) normal (0, 0, 1) x axis (1, 0, 0)
  line L1 (233, 70) -> (233, 59.45)
  line L2 (228.6654, 56.9474) -> (219.5289, 62.2224)
  line L3 (231.5654, 51.9245) -> (228.6654, 56.9474)
  line L4 (217.4654, 27.5026) -> (231.5654, 51.9245)
  line L5 (211.6654, 27.5026) -> (217.4654, 27.5026)
  line L6 (202.5289, 32.7776) -> (211.6654, 27.5026)
  line L7 (211.6654, 22.4974) -> (202.5289, 17.2224)
  line L8 (217.4654, 22.4974) -> (211.6654, 22.4974)
  line L9 (231.5654, -1.9245) -> (217.4654, 22.4974)
  line L10 (228.6654, -6.9474) -> (231.5654, -1.9245)
  line L11 (219.5289, -12.2224) -> (228.6654, -6.9474)
  line L12 (233, -9.45) -> (233, -20)
  line L13 (235.9, -4.4271) -> (233, -9.45)
  line L14 (264.1, -4.4271) -> (235.9, -4.4271)
  line L15 (267, -9.45) -> (264.1, -4.4271)
  line L16 (267, -20) -> (267, -9.45)
  line L17 (271.3346, -6.9474) -> (280.4711, -12.2224)
  line L18 (268.4346, -1.9245) -> (271.3346, -6.9474)
  line L19 (282.5346, 22.4974) -> (268.4346, -1.9245)
  line L20 (288.3346, 22.4974) -> (282.5346, 22.4974)
  line L21 (297.4711, 17.2224) -> (288.3346, 22.4974)
  line L22 (288.3346, 27.5026) -> (297.4711, 32.7776)
  line L23 (282.5346, 27.5026) -> (288.3346, 27.5026)
  line L24 (268.4346, 51.9245) -> (282.5346, 27.5026)
  line L25 (271.3346, 56.9474) -> (268.4346, 51.9245)
  line L26 (280.4711, 62.2224) -> (271.3346, 56.9474)
  line L27 (267, 59.45) -> (267, 70)
  line L28 (264.1, 54.4271) -> (267, 59.45)
  line L29 (235.9, 54.4271) -> (264.1, 54.4271)
  line L30 (233, 59.45) -> (235.9, 54.4271)
  arc A1 centre (250, 25) radius 48.1041 clockwise from (219.5289, 62.2224) to (233, 70)
  arc A2 centre (250, 25) radius 48.1041 clockwise from (202.5289, 17.2224) to (202.5289, 32.7776)
  arc A3 centre (250, 25) radius 48.1041 clockwise from (233, -20) to (219.5289, -12.2224)
  arc A4 centre (250, 25) radius 48.1041 clockwise from (280.4711, -12.2224) to (267, -20)
  arc A5 centre (250, 25) radius 48.1041 clockwise from (297.4711, 32.7776) to (297.4711, 17.2224)
  arc A6 centre (250, 25) radius 48.1041 clockwise from (267, 70) to (280.4711, 62.2224)
  circle C1 centre (250, 25) radius 3
  circle C2 centre (250, 25) radius 10
  dimension "d443" diameter C1 = 6
extrude "Extrude15" add sketch "Sketch7" profile of C1 C2 along normal blind 16
sketch "Sketch8" plane through (0, 0, 21) normal (0, 0, 1) x axis (1, 0, 0)
  circle C1 centre (250, 25) radius 3
  circle C2 centre (250, 25) radius 10
  circle C3 centre (250, 25) radius 6
  dimension "d447" diameter C3 = 12
extrude "Extrude16" add sketch "Sketch8" profile of C1 C3 along normal blind 9
sketch "Sketch9" plane through (94.6509, 2.7725, 57) normal (0, 0, 1) x axis (1, 0, 0)
sketch "Sketch1"
  line L1 (400.1, 49) -> (399.9, 49)
  line L2 (401, 44.9) -> (401, 48.1)
  line L3 (399.9, 44) -> (400.1, 44)
  line L4 (399, 48.1) -> (399, 44.9)
  line L5 (392.2197, 46.7093) -> (393.2085, 43.666)
  line L6 (394.3426, 43.0881) -> (394.5328, 43.1499)
  line L7 (392.9877, 47.9052) -> (392.7975, 47.8434)
  line L8 (395.1106, 44.284) -> (394.1218, 47.3274)
  line L9 (386.2009, 43.2915) -> (388.0818, 40.7026)
  line L10 (389.339, 40.5035) -> (389.5008, 40.6211)
  line L11 (386.5618, 44.6662) -> (386.4, 44.5486)
  line L12 (389.6999, 41.8782) -> (387.819, 44.4671)
  line L13 (381.5329, 38.1811) -> (384.1218, 36.3001)
  line L14 (385.3789, 36.4993) -> (385.4965, 36.6611)
  line L15 (381.4514, 39.6) -> (381.3338, 39.4382)
  line L16 (385.2974, 37.9182) -> (382.7085, 39.7991)
  line L17 (378.6726, 31.8782) -> (381.716, 30.8894)
  line L18 (382.8501, 31.4672) -> (382.9119, 31.6574)
  line L19 (378.1566, 33.2025) -> (378.0948, 33.0123)
  line L20 (382.334, 32.7915) -> (379.2907, 33.7804)
  line L21 (377.9, 25) -> (381.1, 25)
  line L22 (382, 25.9) -> (382, 26.1)
  line L23 (377, 26.1) -> (377, 25.9)
  line L24 (381.1, 27) -> (377.9, 27)
  line L25 (379.2906, 18.2197) -> (382.334, 19.2085)
  line L26 (382.9119, 20.3426) -> (382.8501, 20.5328)
  line L27 (378.0948, 18.9877) -> (378.1566, 18.7975)
  line L28 (381.716, 21.1107) -> (378.6726, 20.1218)
  line L29 (382.7085, 12.2009) -> (385.2973, 14.0819)
  line L30 (385.4964, 15.339) -> (385.3789, 15.5008)
  line L31 (381.3338, 12.5619) -> (381.4514, 12.4001)
  line L32 (384.1218, 15.6999) -> (381.5329, 13.819)
  line L33 (387.8189, 7.533) -> (389.6998, 10.1218)
  line L34 (389.5007, 11.3789) -> (389.3389, 11.4965)
  line L35 (386.4, 7.4514) -> (386.5618, 7.3338)
  line L36 (388.0818, 11.2974) -> (386.2009, 8.7085)
  line L37 (394.1217, 4.6726) -> (395.1106, 7.716)
  line L38 (394.5328, 8.8501) -> (394.3426, 8.9119)
  line L39 (392.7975, 4.1566) -> (392.9877, 4.0948)
  line L40 (393.2085, 8.3341) -> (392.2196, 5.2907)
  line L41 (401, 3.9) -> (401, 7.1)
  line L42 (400.1, 8) -> (399.9, 8)
  line L43 (399.9, 3) -> (400.1, 3)
  line L44 (399, 7.1) -> (399, 3.9)
  line L45 (407.7803, 5.2907) -> (406.7914, 8.334)
  line L46 (405.6574, 8.9119) -> (405.4672, 8.8501)
  line L47 (407.0122, 4.0948) -> (407.2025, 4.1566)
  line L48 (404.8893, 7.716) -> (405.8782, 4.6726)
  line L49 (413.799, 8.7085) -> (411.9181, 11.2974)
  line L50 (410.661, 11.4965) -> (410.4992, 11.3789)
  line L51 (413.4381, 7.3338) -> (413.5999, 7.4514)
  line L52 (410.3001, 10.1218) -> (412.181, 7.5329)
  line L53 (418.467, 13.8189) -> (415.8782, 15.6999)
  line L54 (414.6211, 15.5007) -> (414.5035, 15.3389)
  line L55 (418.5486, 12.4) -> (418.6661, 12.5618)
  line L56 (414.7026, 14.0818) -> (417.2915, 12.2009)
  line L57 (421.3273, 20.1218) -> (418.284, 21.1106)
  line L58 (417.1499, 20.5328) -> (417.0881, 20.3426)
  line L59 (421.8434, 18.7975) -> (421.9052, 18.9877)
  line L60 (417.6659, 19.2085) -> (420.7093, 18.2196)
  line L61 (422.1, 27) -> (418.9, 27)
  line L62 (418, 26.1) -> (418, 25.9)
  line L63 (423, 25.9) -> (423, 26.1)
  line L64 (418.9, 25) -> (422.1, 25)
  line L65 (420.7093, 33.7803) -> (417.6659, 32.7915)
  line L66 (417.0881, 31.6574) -> (417.1499, 31.4672)
  line L67 (421.9052, 33.0123) -> (421.8434, 33.2025)
  line L68 (418.284, 30.8893) -> (421.3274, 31.8782)
  line L69 (417.2915, 39.7991) -> (414.7026, 37.9181)
  line L70 (414.5035, 36.661) -> (414.6211, 36.4992)
  line L71 (418.6662, 39.4381) -> (418.5486, 39.5999)
  line L72 (415.8782, 36.3001) -> (418.4671, 38.181)
  line L73 (412.181, 44.467) -> (410.3001, 41.8782)
  line L74 (410.4992, 40.6211) -> (410.661, 40.5035)
  line L75 (413.6, 44.5486) -> (413.4382, 44.6662)
  line L76 (411.9182, 40.7026) -> (413.7991, 43.2915)
  line L77 (405.8782, 47.3274) -> (404.8894, 44.284)
  line L78 (405.4672, 43.1499) -> (405.6574, 43.0881)
  line L79 (407.2025, 47.8434) -> (407.0123, 47.9052)
  line L80 (406.7915, 43.6659) -> (407.7803, 46.7093)
  circle C1 centre (400, 26) radius 25
  circle C2 centre (400, 26) radius 6
  arc A1 centre (399.9, 48.1) radius 0.9 clockwise from (399, 48.1) to (399.9, 49)
  arc A2 centre (400.1, 48.1) radius 0.9 clockwise from (400.1, 49) to (401, 48.1)
  arc A3 centre (399.9, 44.9) radius 0.9 clockwise from (399.9, 44) to (399, 44.9)
  arc A4 centre (400.1, 44.9) radius 0.9 clockwise from (401, 44.9) to (400.1, 44)
  arc A5 centre (393.2658, 47.0493) radius 0.9 clockwise from (392.9877, 47.9052) to (394.1218, 47.3274)
  arc A6 centre (394.0645, 43.9441) radius 0.9 clockwise from (394.3426, 43.0881) to (393.2085, 43.666)
  arc A7 centre (394.2547, 44.0059) radius 0.9 clockwise from (395.1106, 44.284) to (394.5328, 43.1499)
  arc A8 centre (393.0756, 46.9875) radius 0.9 clockwise from (392.2197, 46.7093) to (392.7975, 47.8434)
  arc A9 centre (387.0909, 43.9381) radius 0.9 clockwise from (386.5618, 44.6662) to (387.819, 44.4671)
  arc A10 centre (388.81, 41.2317) radius 0.9 clockwise from (389.339, 40.5035) to (388.0818, 40.7026)
  arc A11 centre (388.9718, 41.3492) radius 0.9 clockwise from (389.6999, 41.8782) to (389.5008, 40.6211)
  arc A12 centre (386.929, 43.8205) radius 0.9 clockwise from (386.2009, 43.2915) to (386.4, 44.5486)
  arc A13 centre (382.1795, 39.071) radius 0.9 clockwise from (381.4514, 39.6) to (382.7085, 39.7991)
  arc A14 centre (384.6508, 37.0283) radius 0.9 clockwise from (385.3789, 36.4993) to (384.1218, 36.3001)
  arc A15 centre (384.7684, 37.1901) radius 0.9 clockwise from (385.2974, 37.9182) to (385.4965, 36.6611)
  arc A16 centre (382.0619, 38.9092) radius 0.9 clockwise from (381.5329, 38.1811) to (381.3338, 39.4382)
  arc A17 centre (379.0125, 32.9244) radius 0.9 clockwise from (378.1566, 33.2025) to (379.2907, 33.7804)
  arc A18 centre (381.9941, 31.7453) radius 0.9 clockwise from (382.8501, 31.4672) to (381.716, 30.8894)
  arc A19 centre (382.0559, 31.9355) radius 0.9 clockwise from (382.334, 32.7915) to (382.9119, 31.6574)
  arc A20 centre (378.9507, 32.7342) radius 0.9 clockwise from (378.6726, 31.8782) to (378.0948, 33.0123)
  arc A21 centre (377.9, 26.1) radius 0.9 clockwise from (377, 26.1) to (377.9, 27)
  arc A22 centre (381.1, 25.9) radius 0.9 clockwise from (382, 25.9) to (381.1, 25)
  arc A23 centre (381.1, 26.1) radius 0.9 clockwise from (381.1, 27) to (382, 26.1)
  arc A24 centre (377.9, 25.9) radius 0.9 clockwise from (377.9, 25) to (377, 25.9)
  arc A25 centre (378.9507, 19.2659) radius 0.9 clockwise from (378.0948, 18.9877) to (378.6726, 20.1218)
  arc A26 centre (382.0559, 20.0645) radius 0.9 clockwise from (382.9119, 20.3426) to (382.334, 19.2085)
  arc A27 centre (381.9941, 20.2547) radius 0.9 clockwise from (381.716, 21.1107) to (382.8501, 20.5328)
  arc A28 centre (379.0125, 19.0756) radius 0.9 clockwise from (379.2906, 18.2197) to (378.1566, 18.7975)
  arc A29 centre (382.0619, 13.0909) radius 0.9 clockwise from (381.3338, 12.5619) to (381.5329, 13.819)
  arc A30 centre (384.7683, 14.81) radius 0.9 clockwise from (385.4964, 15.339) to (385.2973, 14.0819)
  arc A31 centre (384.6508, 14.9718) radius 0.9 clockwise from (384.1218, 15.6999) to (385.3789, 15.5008)
  arc A32 centre (382.1795, 12.9291) radius 0.9 clockwise from (382.7085, 12.2009) to (381.4514, 12.4001)
  arc A33 centre (386.929, 8.1795) radius 0.9 clockwise from (386.4, 7.4514) to (386.2009, 8.7085)
  arc A34 centre (388.9717, 10.6508) radius 0.9 clockwise from (389.5007, 11.3789) to (389.6998, 10.1218)
  arc A35 centre (388.8099, 10.7684) radius 0.9 clockwise from (388.0818, 11.2974) to (389.3389, 11.4965)
  arc A36 centre (387.0908, 8.062) radius 0.9 clockwise from (387.8189, 7.533) to (386.5618, 7.3338)
  arc A37 centre (393.0756, 5.0126) radius 0.9 clockwise from (392.7975, 4.1566) to (392.2196, 5.2907)
  arc A38 centre (394.2546, 7.9941) radius 0.9 clockwise from (394.5328, 8.8501) to (395.1106, 7.716)
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  point P2 (400, 26)
  point P4 (399, 49)
  point P6 (399, 44)
  point P5 (401, 44)
  dimension "d462" diameter C2 = 12
  dimension "d463" distance P2 L1 = 23
  dimension "d464" distance P4 P6 = 5
  dimension "d465" distance P5 P6 = 2
  dimension "d466" radius A1 = 0.9
  dimension "d467" radius A2 = 0.9
  dimension "d468" radius A3 = 0.9
  dimension "d469" radius A4 = 0.9
  dimension "d471" C-Pattern1-Angle = 360
extrude "Extrude1" new body sketch "Sketch1" blind 2
joint "Assemble11" alignAngle 0 alignOffsetX 0 alignOffsetY 0 alignOffsetZ 0
sketch "Sketch1" plane through (0, 0, 0) normal (0, 1, 0) x axis (1, 0, 0)
  line L1 (445, -10) -> (420, -10)
  line L2 (445, -30) -> (445, -10)
  line L3 (420, -30) -> (445, -30)
  line L4 (420, -10) -> (420, -30)
  line L5 (427, -11) -> (421, -11)
  line L6 (427, -29) -> (427, -11)
  line L7 (421, -29) -> (427, -29)
  line L8 (421, -11) -> (421, -29)
  line L9 (421, -29) -> (427, -29)
  line L10 (421, -25) -> (421, -29)
  line L11 (427, -25) -> (421, -25)
  line L12 (427, -29) -> (427, -25)
  line L13 (421, -11) -> (427, -11)
  line L14 (421, -15) -> (421, -11)
  line L15 (427, -15) -> (421, -15)
  line L16 (427, -11) -> (427, -15)
  point P2 (420, -10)
  point P3 (445, -10)
  point P5 (420, -30)
  dimension "d486" distance P2 P3 = 25
  dimension "d487" distance P2 P5 = 20
extrude "Extrude1" new body sketch "Sketch1" profile of L1 L2 L3 L4 L5 L6 L7 L8 L9 L10 L12 L13 L14 L16 along normal blind 2
extrude "Extrude2" add sketch "Sketch1" profile of L5 L6 L7 L8 L9 L10 L11 L12 L13 L14 L15 L16 along normal blind 18
extrude "Extrude3" add sketch "Sketch1" profile of L6 L8 L11 L15 along normal blind 5
joint "Assemble12" alignAngle 0 alignOffsetX 0 alignOffsetY 0 alignOffsetZ 0
move "Move1"
sketch "Sketch2" plane through (0, 63.4507, 0) normal (0, 1, 0) x axis (-1, 0, 0)
  line L1 (-2.8187, -132.0831) -> (22.1813, -132.0831)
  line L2 (-2.8187, -152.0831) -> (-2.8187, -132.0831)
  line L3 (22.1813, -152.0831) -> (-2.8187, -152.0831)
  line L4 (22.1813, -132.0831) -> (22.1813, -152.0831)
  circle C1 centre (19.6813, -149.5831) radius 1.5
  circle C2 centre (19.6813, -134.5831) radius 1.5
  point P6 (19.6813, -149.5831)
  point P7 (19.6813, -134.5831)
  dimension "d506" distance L4 P6 = 2.5
  dimension "d507" diameter C1 = 3
  dimension "d508" distance L3 P6 = 2.5
  dimension "d509" distance L4 P7 = 2.5
  dimension "d510" distance L1 P7 = 2.5
extrude "Extrude4" cut sketch "Sketch2" profile of C1 C2 against normal blind 2
sketch "Sketch3" plane through (0, 63.4507, 0) normal (0, 1, 0) x axis (-1, 0, 0)
  line L1 (-2.8187, -132.0831) -> (22.1813, -132.0831)
  line L2 (-2.8187, -152.0831) -> (-2.8187, -132.0831)
  line L3 (22.1813, -152.0831) -> (-2.8187, -152.0831)
  line L4 (22.1813, -132.0831) -> (22.1813, -152.0831)
  circle C1 centre (19.6813, -149.5831) radius 1.5
  circle C2 centre (19.6813, -134.5831) radius 1.5
  point P2 (19.6813, -149.5831)
  point P3 (19.6813, -134.5831)
  dimension "d513" distance P2 P3 = 15
sketch "Sketch1" plane through (0, 0, 0) normal (0, 1, 0) x axis (1, 0, 0)
  line L1 (185, 100.0035) -> (149.982, 100.0035)
  line L2 (149.982, 100.0035) -> (177.8189, 148.2184)
  line L3 (185, 100.0035) -> (185, 148.2184)
  line L4 (191.8189, 148.2184) -> (185, 148.2184)
  line L5 (191.8189, 172.4709) -> (191.8189, 148.2184)
  line L6 (177.8189, 172.4709) -> (191.8189, 172.4709)
  line L7 (177.8189, 148.2184) -> (177.8189, 172.4709)
  circle C1 centre (184.8189, 170.4709) radius 1.5
  circle C2 centre (184.9419, 155.4714) radius 1.5
  circle C3 centre (181, 104.0035) radius 2
  circle C4 centre (157, 104.0035) radius 2
  circle C5 centre (181, 140) radius 2
  point P5 (177.8189, 148.2184)
  point P6 (191.8189, 148.2184)
  point P10 (184.8189, 170.4709)
  point P11 (184.9419, 155.4714)
  point P12 (181, 104.0035)
  point P13 (157, 104.0035)
  dimension "d514" distance P5 P6 = 14
  dimension "d515" diameter C1 = 3
  dimension "d516" diameter C2 = 3
  dimension "d517" distance P10 P11 = 15
  dimension "d518" distance L6 P10 = 2
  dimension "d519" distance L7 P10 = 7
  dimension "d520" diameter C3 = 4
  dimension "d521" distance L1 P12 = 4
  dimension "d522" distance L1 P13 = 4
extrude "Extrude1" new body sketch "Sketch1" along normal blind 2
sketch "Sketch1" plane through (0, 0, 0) normal (1, 0, 0) x axis (0, 0, -1)
sketch "Sketch2" plane through (0, 0, 0) normal (1, 0, 0) x axis (0, 0, -1)
sketch "Sketch3" plane through (0, 0, 0) normal (0, 1, 0) x axis (1, 0, 0)
  circle C1 centre (215, 170) radius 1.5
  circle C2 centre (215, 155) radius 1.5
  point P2 (215, 170)
  point P3 (215, 155)
  dimension "d525" diameter C1 = 3
  dimension "d526" diameter C2 = 3
  dimension "d527" distance P2 P3 = 15
sketch "Sketch4" plane through (0, 0, 0) normal (0, 1, 0) x axis (1, 0, 0)
  circle C1 centre (270, 175) radius 1.5
  dimension "d530" diameter C1 = 3
extrude "Extrude2" new body sketch "Sketch4" along normal blind 6
copy_paste_bodies "CopyPasteBodies1"
move "Move1"
joint "Assemble13" alignAngle 0 alignOffsetX 0 alignOffsetY 0 alignOffsetZ 0
joint "Assemble14" alignAngle 0 alignOffsetX 0 alignOffsetY 0 alignOffsetZ 0
joint "Assemble15" alignAngle 0 alignOffsetX 0 alignOffsetY 0 alignOffsetZ 0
